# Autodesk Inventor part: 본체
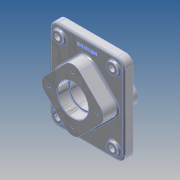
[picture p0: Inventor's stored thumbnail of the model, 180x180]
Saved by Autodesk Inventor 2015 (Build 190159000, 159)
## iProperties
Created: 2026-07
Part Number: 본체
Material: 알루미늄 6061
Document SubType Name: Modeling
Designer: USER
Density: 2.7 g/cm^3
Appearance: 알루미늄 - 평지
Mass: 2132.41 g
Surface Area: 955.114 cm^2
Volume: 789.782 cm^3
Author: USER
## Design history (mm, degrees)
sketch "스케치1"
  geometry: L1 (75, 90)-(-75, 90); L2 (-75, 90)-(-75, -90); L3 (-75, -90)-(75, -90); L4 (75, -90)-(75, 90); L5 (75, 90)-(-75, -90); L6 (-75, 90)-(75, -90); 1 further point
  constraints: 12 end point, 2 midpoint, 2 parallel, 1 horizontal, 1 perpendicular
  dimensions: "d0" = 150 distance of L3.end L2.end; "d1" = 180 distance of L2.end L1.end
extrude "돌출1" new body sketch "스케치1" distance "d2" = 18; taper "d3" = 0 deg
sketch "스케치2"
  geometry: L1 (0, -70.711)-(-70.711, 0); L2 (-70.711, 0)-(0, 70.711); L3 (0, 70.711)-(70.711, 0); L4 (70.711, 0)-(0, -70.711); 2 further points
  constraints: 8 end point, 2 horizontal alignment, 1 coincident, 1 vertical alignment, 9 other
  dimensions: "d4" = 100 distance between parallel lines of L1 L3
extrude "돌출2" join sketch "스케치2" distance "d5" = 29; taper "d6" = 0 deg
sketch "스케치3"
  geometry: L1 (0, 70.711)-(70.711, 0); L2 (70.711, 0)-(0, -70.711); L3 (0, -70.711)-(-70.711, 0); L4 (-70.711, 0)-(0, 70.711); 2 further points
  constraints: 8 end point, 2 horizontal alignment, 2 vertical alignment, 1 coincident, 9 other
  dimensions: "d7" = 100 distance between parallel lines of L3 L1
extrude "돌출3" join sketch "스케치3" distance "d8" = 23; taper "d9" = 0 deg
fillet "모깎기1" dims "d10" = 15
fillet "모깎기2" dims "d11" = 20
fillet "모깎기3" dims "d12" = 20
hole "구멍1" diameter "d15" = 54; stored, may be unused: countersink angle "d19" = 90 deg, drill point angle "d21" = 0 deg; dims "d13" = 50, "d14" = 50, "d16" = 6, "d17" = 62, "d18" = 22, "d20" = 8
hole "구멍2" diameter "d24" = 62; stored, may be unused: countersink angle "d28" = 90 deg, drill point angle "d30" = 0 deg; dims "d22" = 50, "d23" = 50, "d25" = 6, "d26" = 62, "d27" = 22, "d29" = 22
sketch "스케치4"
  geometry: L1 (0, 0)-(0, 48)
  constraints: 2 end point, 1 vertical
  dimensions: "d31" = 48 distance of L1.start L1.end
hole "구멍3" sketch "스케치4" at (0, 48) diameter "d32" = 4.917; stored, may be unused: countersink angle "d36" = 90 deg, drill point angle "d38" = 118 deg; dims "d33" = 10, "d34" = 62, "d35" = 22, "d37" = 13
sketch "스케치5"
  geometry: L1 (0, 0)-(0, -48); C1 r 2.458 at (0, -48) reference
  constraints: 2 end point, 1 vertical
  dimensions: "d42" = 48 distance of L1.start L1.end (derived)
hole "구멍4" sketch "스케치5" at (0, -48) diameter "d43" = 4.917; stored, may be unused: countersink angle "d47" = 90 deg, drill point angle "d49" = 118 deg; dims "d44" = 10, "d45" = 62, "d46" = 22, "d48" = 13
sketch "스케치6"
  geometry: L1 (-75, -75)-(-75, 75) reference; L2 (-60, 90)-(60, 90) reference; L3 (75, 75)-(75, -75) reference; L4 (60, -90)-(-60, -90) reference; L5 (56.569, 14.142)-(14.142, 56.569) reference; L6 (-14.142, 56.569)-(-56.569, 14.142) reference; L7 (-56.569, -14.142)-(-14.142, -56.569) reference; L8 (14.142, -56.569)-(56.569, -14.142) reference; L9 (56.569, -14.142)-(14.142, -56.569) reference; L10 (-14.142, -56.569)-(-56.569, -14.142) reference; L11 (-56.569, 14.142)-(-14.142, 56.569) reference; L12 (14.142, 56.569)-(56.569, 14.142) reference; L13 (60, -90)-(-60, -90) reference; L14 (-75, -75)-(-75, 75) reference; L15 (-60, 90)-(60, 90) reference; L16 (75, 75)-(75, -75) reference; C1 r 27 at (0, 0) reference; C2 r 11 at (-55, 70); A1 r 15 centre (-60, -75) between (-75, -75) and (-60, -90) reference; A2 r 15 centre (-60, 75) between (-60, 90) and (-75, 75) reference; A3 r 15 centre (60, 75) between (75, 75) and (60, 90) reference; A4 r 15 centre (60, -75) between (60, -90) and (75, -75) reference; A5 r 20 centre (0, 42.426) between (14.142, 56.569) and (-14.142, 56.569) reference; A6 r 20 centre (-42.426, 0) between (-56.569, 14.142) and (-56.569, -14.142) reference; A7 r 20 centre (0, -42.426) between (-14.142, -56.569) and (14.142, -56.569) reference; A8 r 20 centre (42.426, 0) between (56.569, -14.142) and (56.569, 14.142) reference; A9 r 20 centre (42.426, 0) between (56.569, -14.142) and (56.569, 14.142) reference; A10 r 20 centre (0, -42.426) between (-14.142, -56.569) and (14.142, -56.569) reference; A11 r 20 centre (-42.426, 0) between (-56.569, 14.142) and (-56.569, -14.142) reference; A12 r 20 centre (0, 42.426) between (14.142, 56.569) and (-14.142, 56.569) reference; A13 r 15 centre (60, -75) between (60, -90) and (75, -75) reference; A14 r 15 centre (-60, -75) between (-75, -75) and (-60, -90) reference; A15 r 15 centre (-60, 75) between (-60, 90) and (-75, 75) reference; A16 r 15 centre (60, 75) between (75, 75) and (60, 90) reference; 1 further point
  constraints: 1 centre point
  dimensions: "d53" = 22 diameter of C2; "d54" = 55 horizontal distance of C2.centre point (0, 0); "d55" = 70 vertical distance of point (0, 0) C2.centre
extrude "돌출4" join sketch "스케치6" distance "d56" = 5; taper "d57" = 0 deg
hole "구멍5" diameter "d60" = 11; stored, may be unused: countersink angle "d64" = 90 deg, drill point angle "d66" = 0 deg; dims "d58" = 10, "d59" = 10, "d61" = 6, "d62" = 4, "d63" = 2, "d65" = 8
sketch "스케치7"
  geometry: L1 (-60, 90)-(60, 90) reference; 2 further points
  constraints: 1 vertical alignment, 1 other
  dimensions: "d73" = 15 distance from line of point (0, 75) L1
feature "엠보싱1" sketch "스케치7" dims "d0" = 150, "d1" = 180, "d7" = 100, "d74" = 0.5, "d75" = 0
chamfer "모따기1" distance "d76" = 1; stored, may be unused: second distance "d77" = 2, angle "d78" = 45 deg
fillet "모깎기4" dims "d79" = 1
fillet "모깎기5" dims "d80" = 3
fillet "모깎기6" dims "d81" = 3
fillet "모깎기7" dims "d82" = 3
fillet "모깎기8" dims "d83" = 3
node "솔리드1"
pattern_circular "원형 패턴1" dims angle "d40" = 360 deg
pattern_circular "원형 패턴2" dims angle "d51" = 360 deg
pattern_linear "직사각형 패턴1"
node "투영된 루프1"
node "절단 모서리 투영1"
